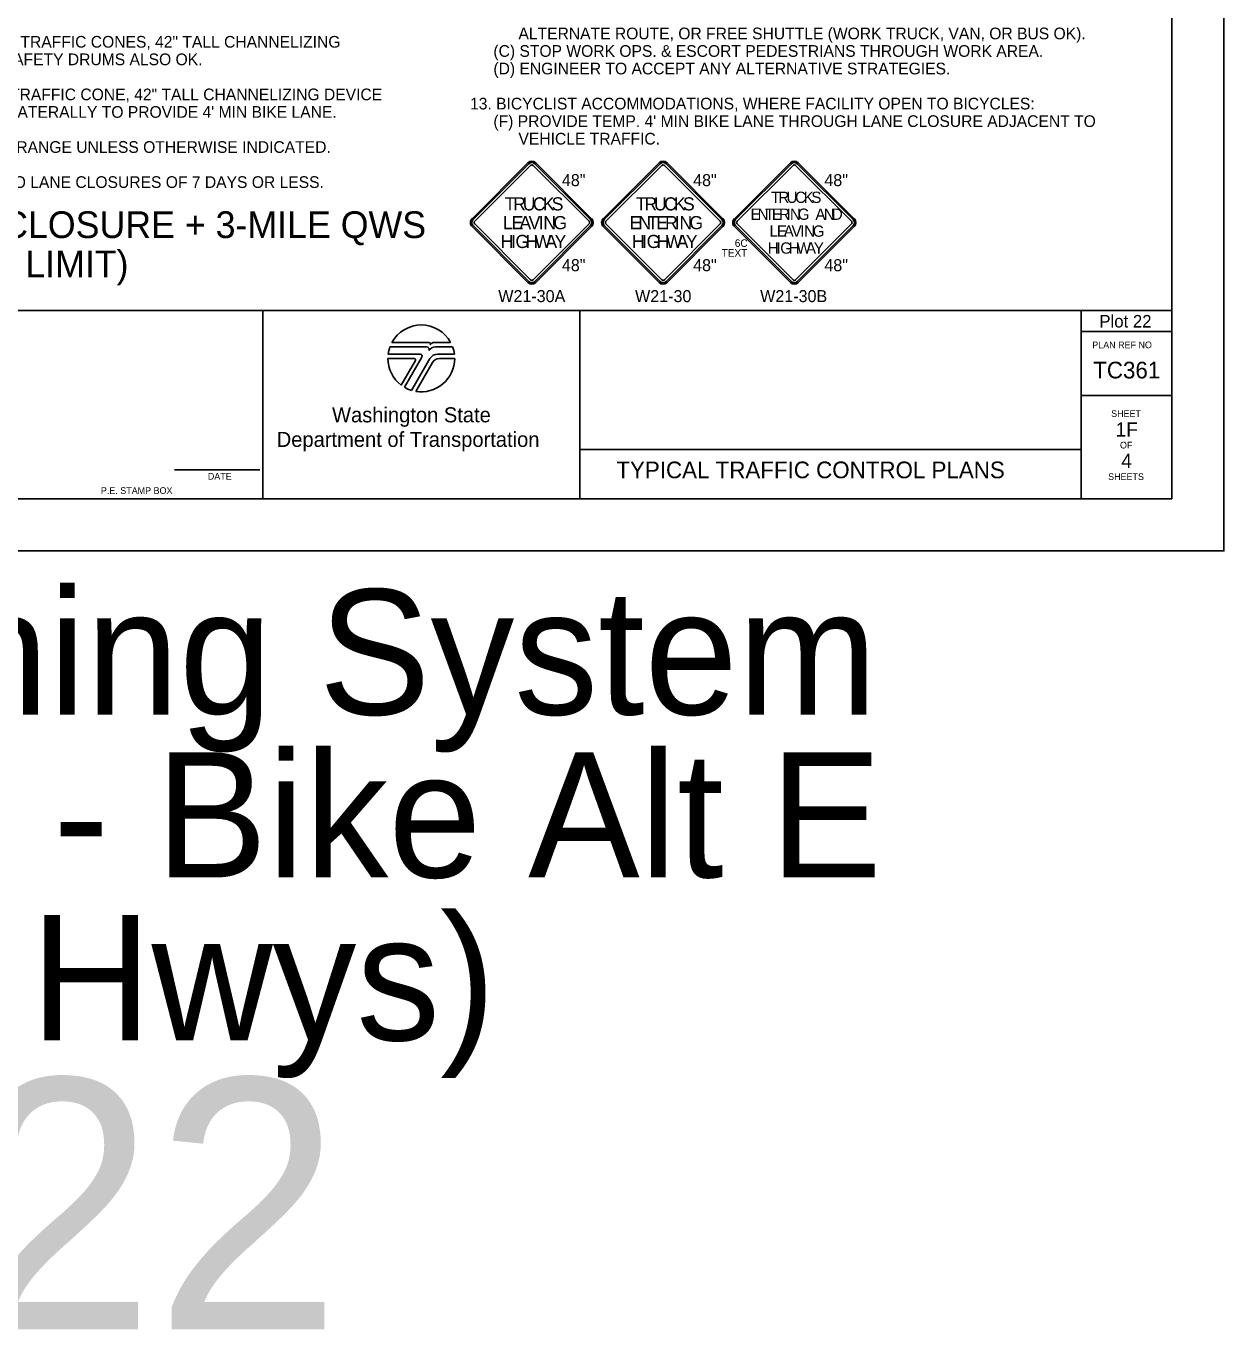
# Model space of a CAD drawing. Extents: x 99958 to 100176, y 99935 to 100011.
# Drawn here: x 100028.89 to 100036.06, y 99935.01 to 99942.83 of the extents above; entities that cross this region are included whole.
import ezdxf

# ---------------------------------------------------------------- set-up
doc = ezdxf.new("R2010")
doc.units = 0
for name, color, linetype in [('SH_DE_DetailHeading1Text', 7, 'Continuous'), ('SH_GI_GeneralNotesBodyText', 7, 'Continuous'), ('SH_GI_PlotLimits', 7, 'Continuous'), ('SH_GI_SheetBorder', 7, 'Continuous'), ('SH_GI_SheetLocationText', 7, 'Continuous'), ('SH_GI_SheetTextInCells', 7, 'Continuous'), ('SH_GI_TitleBlockText', 7, 'Continuous'), ('SH_GI_WSDOTLogo', 7, 'Continuous'), ('TR_SN_ConstructionSigns', 7, 'Continuous')]:
    doc.layers.add(name, color=color, linetype=linetype)

msp = doc.modelspace()

# ---------------------------------------------------------------- linework, layer by layer
at = {"layer": 'SH_GI_PlotLimits'}
msp.add_lwpolyline([(100019.0625, 99939.6875), (100036.0625, 99939.6875), (100036.0625, 99950.6875), (100019.0625, 99950.6875)], close=True, dxfattribs=at)
at = {"layer": 'SH_GI_SheetBorder'}
for p, q in [((100035.75, 99950.375), (100035.75, 99940)), ((100020, 99941.1259), (100035.75, 99941.1259)), ((100030.3089, 99941.1259), (100030.3089, 99940)), ((100032.2055, 99941.1259), (100032.2055, 99940)), ((100035.2079, 99941.1259), (100035.2079, 99940)), ((100035.2079, 99941.0008), (100035.75, 99941.0008)), ((100035.2079, 99940.6176), (100035.75, 99940.6176)), ((100032.2055, 99940.2955), (100035.2079, 99940.2955)), ((100029.7797, 99940.1733), (100030.2914, 99940.1733)), ((100020, 99940), (100035.75, 99940))]:
    msp.add_line(p, q, dxfattribs=at)
at = {"layer": 'SH_GI_WSDOTLogo'}
for p, q in [((100031.2894, 99940.9094), (100031.0697, 99940.9094)), ((100031.303, 99940.9354), (100031.0815, 99940.9354)), ((100031.433, 99940.9354), (100031.3351, 99940.9354)), ((100031.343, 99940.9094), (100031.3429, 99940.9094)), ((100031.4448, 99940.9094), (100031.343, 99940.9094)), ((100031.0572, 99940.84), (100031.2148, 99940.84)), ((100031.059, 99940.8661), (100031.2496, 99940.8661)), ((100031.222, 99940.8277), (100031.1364, 99940.6807)), ((100031.261, 99940.8464), (100031.1567, 99940.6672)), ((100031.1989, 99940.6487), (100031.3089, 99940.839)), ((100031.3558, 99940.8661), (100031.4555, 99940.8661)), ((100031.3655, 99940.8394), (100031.4572, 99940.8394)), ((100031.2244, 99940.6428), (100031.3242, 99940.8156))]:
    msp.add_line(p, q, dxfattribs=at)
for centre, radius, start, end in [((100031.2572, 99940.84), 0.2, 28.47865, 151.53204), ((100031.2572, 99940.84), 0.2, 159.69598, 172.50569), ((100031.2894, 99940.8946), 0.0148, 327.8418, 89.99855), ((100031.3429, 99940.861), 0.0484, 89.99529, 147.82376), ((100031.303, 99940.9263), 0.00903, 329.87418, 90.00328), ((100031.3352, 99940.9066), 0.0287, 90.00721, 148.16763), ((100031.2572, 99940.84), 0.2, 7.49431, 20.29406), ((100031.2572, 99940.84), 0.2, 179.99864, 232.84327), ((100031.2149, 99940.8318), 0.0082, 329.74356, 90), ((100031.2572, 99940.84), 0.2, 260.54554, 359.80857), ((100031.2497, 99940.853), 0.0131, 329.76834, 90), ((100031.3558, 99940.8119), 0.0542, 90, 149.99738), ((100031.3654, 99940.7918), 0.0476, 90, 150.05432), ((100031.2572, 99940.84), 0.2, 239.79292, 253.0448)]:
    msp.add_arc(centre, radius, start, end, dxfattribs=at)
at = {"layer": 'TR_SN_ConstructionSigns'}
for p, q in [((100031.8955, 99942.0107), (100031.5613, 99941.6766)), ((100031.9014, 99942.0048), (100031.5673, 99941.6707)), ((100032.2713, 99941.6707), (100031.9372, 99942.0048)), ((100032.2773, 99941.6766), (100031.9432, 99942.0107)), ((100032.6812, 99942.0107), (100032.3471, 99941.6766)), ((100032.6871, 99942.0048), (100032.353, 99941.6707)), ((100033.057, 99941.6707), (100032.7229, 99942.0048)), ((100033.063, 99941.6766), (100032.7289, 99942.0107)), ((100033.4669, 99942.0107), (100033.1328, 99941.6766)), ((100033.4729, 99942.0048), (100033.1387, 99941.6707)), ((100033.8428, 99941.6707), (100033.5087, 99942.0048)), ((100033.8487, 99941.6766), (100033.5146, 99942.0107)), ((100031.5773, 99941.6607), (100031.9114, 99941.9948)), ((100031.9273, 99941.9948), (100032.2614, 99941.6607)), ((100032.363, 99941.6607), (100032.6971, 99941.9948)), ((100032.713, 99941.9948), (100033.0471, 99941.6607)), ((100033.1487, 99941.6607), (100033.4828, 99941.9948)), ((100033.4987, 99941.9948), (100033.8328, 99941.6607)), ((100031.5613, 99941.6289), (100031.8955, 99941.2948)), ((100031.5673, 99941.6349), (100031.9014, 99941.3008)), ((100031.9114, 99941.3107), (100031.5773, 99941.6448)), ((100032.2614, 99941.6448), (100031.9273, 99941.3107)), ((100031.9372, 99941.3008), (100032.2713, 99941.6349)), ((100031.9432, 99941.2948), (100032.2773, 99941.6289)), ((100032.3471, 99941.6289), (100032.6812, 99941.2948)), ((100032.353, 99941.6349), (100032.6871, 99941.3008)), ((100032.6971, 99941.3107), (100032.363, 99941.6448)), ((100033.0471, 99941.6448), (100032.713, 99941.3107)), ((100032.7229, 99941.3008), (100033.057, 99941.6349)), ((100032.7289, 99941.2948), (100033.063, 99941.6289)), ((100033.1328, 99941.6289), (100033.4669, 99941.2948)), ((100033.1387, 99941.6349), (100033.4729, 99941.3008)), ((100033.4828, 99941.3107), (100033.1487, 99941.6448)), ((100033.8328, 99941.6448), (100033.4987, 99941.3107)), ((100033.5087, 99941.3008), (100033.8428, 99941.6349)), ((100033.5146, 99941.2948), (100033.8487, 99941.6289))]:
    msp.add_line(p, q, dxfattribs=at)
for centre, radius, start, end in [((100031.9193, 99941.9869), 0.0338, 45, 135), ((100031.9193, 99941.9869), 0.0253, 45, 135), ((100031.9193, 99941.9869), 0.0113, 45, 135), ((100032.705, 99941.9869), 0.0338, 45, 135), ((100032.705, 99941.9869), 0.0253, 45, 135), ((100032.705, 99941.9869), 0.0113, 45, 135), ((100033.4908, 99941.9869), 0.0338, 45, 135), ((100033.4908, 99941.9869), 0.0253, 45, 135), ((100033.4908, 99941.9869), 0.0113, 45, 135), ((100031.5852, 99941.6528), 0.0338, 135, 225.00001), ((100031.5852, 99941.6528), 0.0253, 135, 225.00001), ((100031.5852, 99941.6528), 0.0113, 135, 225.00001), ((100032.2534, 99941.6528), 0.0113, 315.00002, 45), ((100032.2534, 99941.6528), 0.0253, 315.00002, 45), ((100032.2534, 99941.6528), 0.0338, 315.00001, 45.00001), ((100032.3709, 99941.6528), 0.0338, 135, 225.00001), ((100032.3709, 99941.6528), 0.0253, 135, 225.00001), ((100032.3709, 99941.6528), 0.0113, 135, 225.00001), ((100033.0391, 99941.6528), 0.0113, 315.00002, 45), ((100033.0391, 99941.6528), 0.0253, 315.00002, 45), ((100033.0391, 99941.6528), 0.0338, 315.00001, 45.00001), ((100033.1566, 99941.6528), 0.0338, 135, 225.00001), ((100033.1566, 99941.6528), 0.0253, 135, 225.00001), ((100033.1566, 99941.6528), 0.0113, 135, 225.00001), ((100033.8249, 99941.6528), 0.0113, 315.00002, 45), ((100033.8249, 99941.6528), 0.0253, 315.00002, 45), ((100033.8249, 99941.6528), 0.0338, 315.00001, 45.00001), ((100031.9193, 99941.3187), 0.0338, 225.00001, 315.00001), ((100031.9193, 99941.3187), 0.0253, 225.00001, 315.00002), ((100031.9193, 99941.3187), 0.0113, 225.00001, 315.00002), ((100032.705, 99941.3187), 0.0338, 225.00001, 315.00001), ((100032.705, 99941.3187), 0.0253, 225.00001, 315.00002), ((100032.705, 99941.3187), 0.0113, 225.00001, 315.00002), ((100033.4908, 99941.3187), 0.0338, 225.00001, 315.00001), ((100033.4908, 99941.3187), 0.0253, 225.00001, 315.00002), ((100033.4908, 99941.3187), 0.0113, 225.00001, 315.00002)]:
    msp.add_arc(centre, radius, start, end, dxfattribs=at)

# ---------------------------------------------------------------- texts
at = {"layer": 'SH_DE_DetailHeading1Text'}
for s, p in [('4-LANE DIVIDED HIGHWAYS: SINGLE RIGHT LANE CLOSURE + 3-MILE QWS', (100023.5403, 99941.5606)), ('(45+ MPH, MAINTAIN EXISTING SPEED LIMIT)', (100024.8739, 99941.3259))]:
    msp.add_text(s, height=0.16, rotation=360, dxfattribs=at).set_placement(p)
at = {"layer": 'SH_GI_GeneralNotesBodyText'}
for s, p in [('ALTERNATE ROUTE, OR FREE SHUTTLE (WORK TRUCK, VAN, OR BUS OK).', (100031.839, 99942.7506)), ('7. 28" TRAFFIC CONES, 36" TRAFFIC CONES, 42" TALL CHANNELIZING ', (100027.6204, 99942.7006)), ('(C) STOP WORK OPS. & ESCORT PEDESTRIANS THROUGH WORK AREA.', (100031.689, 99942.6456)), ('DEVICES, OR TRAFFIC SAFETY DRUMS ALSO OK.', (100027.7004, 99942.5956)), ('(D) ENGINEER TO ACCEPT ANY ALTERNATIVE STRATEGIES.', (100031.689, 99942.5406)), ('8. 28" TRAFFIC CONE, 36" TRAFFIC CONE, 42" TALL CHANNELIZING DEVICE ', (100027.6204, 99942.3856)), ('13. BICYCLIST ACCOMMODATIONS, WHERE FACILITY OPEN TO BICYCLES:', (100031.549, 99942.3306)), ("OK. DEVICE MAY SHIFT LATERALLY TO PROVIDE 4' MIN BIKE LANE.", (100027.7004, 99942.2806)), ("(F) PROVIDE TEMP. 4' MIN BIKE LANE THROUGH LANE CLOSURE ADJACENT TO ", (100031.689, 99942.2256)), ('VEHICLE TRAFFIC.', (100031.839, 99942.1206)), ('9. SIGNS ARE BLACK ON ORANGE UNLESS OTHERWISE INDICATED.', (100027.6204, 99942.0706)), ('10. PLAN IS APPLICABLE TO LANE CLOSURES OF 7 DAYS OR LESS.', (100027.6204, 99941.8606))]:
    msp.add_text(s, height=0.07, rotation=360, dxfattribs=at).set_placement(p)
at = {"layer": 'SH_GI_SheetBorder'}
msp.add_text('PLAN REF NO', height=0.040032, dxfattribs=at).set_placement((100035.2747, 99940.9008))
at = {"layer": 'SH_GI_SheetLocationText'}
for s, height, p in [('Plot 22', 0.075, (100035.3171, 99941.025)), ('Plot 22', 0.075, (100035.3171, 99941.025)), ('3-Mile Queue Warning System', 0.75, (100020.3313, 99938.7071)), ('Right Lane Closure - Bike Alt E', 0.75, (100020.19, 99937.7321)), ('(45+ mph ML Hwys)', 0.75, (100022.7028, 99936.7571)), ('Plot 22', 1.5, (100024.5332, 99935.0267))]:
    msp.add_text(s, height=height, dxfattribs=at).set_placement(p)
at = {"layer": 'SH_GI_SheetTextInCells'}
for s, height, p in [('Washington State', 0.090072, (100030.7229, 99940.4571)), ('SHEET', 0.04003, (100035.3877, 99940.4896)), ('Department of Transportation', 0.090072, (100030.3916, 99940.3101)), ('OF', 0.04003, (100035.4406, 99940.3008)), ('DATE', 0.04003, (100029.9794, 99940.1141)), ('SHEETS', 0.04003, (100035.3698, 99940.112)), ('P.E. STAMP BOX', 0.040032, (100029.339, 99940.0286))]:
    msp.add_text(s, height=height, dxfattribs=at).set_placement(p)
at = {"layer": 'SH_GI_TitleBlockText'}
for s, height, p in [('TC361', 0.1, (100035.2803, 99940.72)), ('1F', 0.085, (100035.4148, 99940.3723)), ('TYPICAL TRAFFIC CONTROL PLANS', 0.1, (100032.4251, 99940.1224)), ('4', 0.085, (100035.4485, 99940.1843))]:
    msp.add_text(s, height=height, dxfattribs=at).set_placement(p)
at = {"layer": 'TR_SN_ConstructionSigns'}
for s, p in [('48"', (100032.0991, 99941.8713)), ('48"', (100032.8848, 99941.8713)), ('48"', (100033.6706, 99941.8713)), ('48"', (100032.0991, 99941.3622)), ('48"', (100032.8848, 99941.3622)), ('48"', (100033.6706, 99941.3622)), ('W21-30A', (100031.7182, 99941.1769)), ('W21-30', (100032.5373, 99941.1769)), ('W21-30B', (100033.2863, 99941.1769))]:
    msp.add_text(s, height=0.072, rotation=360, dxfattribs=at).set_placement(p)
for s, height, p in [('T', 0.0787, (100031.7563, 99941.7259)), ('R', 0.0787, (100031.8075, 99941.7259)), ('U', 0.0787, (100031.865, 99941.7259)), ('C', 0.0787, (100031.9248, 99941.7259)), ('K', 0.0787, (100031.9847, 99941.7259)), ('S', 0.0787, (100032.0382, 99941.7259)), ('T', 0.0787, (100032.542, 99941.7259)), ('R', 0.0787, (100032.5932, 99941.7259)), ('U', 0.0787, (100032.6507, 99941.7259)), ('C', 0.0787, (100032.7106, 99941.7259)), ('K', 0.0787, (100032.7704, 99941.7259)), ('S', 0.0787, (100032.824, 99941.7259)), ('T', 0.0675, (100033.351, 99941.7709)), ('R', 0.0675, (100033.3949, 99941.7709)), ('U', 0.0675, (100033.4442, 99941.7709)), ('C', 0.0675, (100033.4955, 99941.7709)), ('K', 0.0675, (100033.5468, 99941.7709)), ('S', 0.0675, (100033.5927, 99941.7709)), ('L', 0.0787, (100031.7465, 99941.6134)), ('E', 0.0787, (100031.7977, 99941.6134)), ('A', 0.0787, (100031.8449, 99941.6134)), ('V', 0.0787, (100031.9, 99941.6134)), ('I', 0.0787, (100031.9599, 99941.6134)), ('N', 0.0787, (100031.9882, 99941.6134)), ('G', 0.0787, (100032.0481, 99941.6134)), ('E', 0.0787, (100032.5034, 99941.6134)), ('N', 0.0787, (100032.557, 99941.6134)), ('T', 0.0787, (100032.6121, 99941.6134)), ('E', 0.0787, (100032.6633, 99941.6134)), ('R', 0.0787, (100032.7169, 99941.6134)), ('I', 0.0787, (100032.7743, 99941.6134)), ('N', 0.0787, (100032.8027, 99941.6134)), ('G', 0.0787, (100032.8625, 99941.6134)), ('E', 0.0675, (100033.2286, 99941.6696)), ('N', 0.0675, (100033.271, 99941.6696)), ('T', 0.0675, (100033.3154, 99941.6696)), ('E', 0.0675, (100033.3565, 99941.6696)), ('R', 0.0675, (100033.3989, 99941.6696)), ('I', 0.0675, (100033.4448, 99941.6696)), ('N', 0.0675, (100033.4646, 99941.6696)), ('G', 0.0675, (100033.5118, 99941.6696)), ('A', 0.0675, (100033.6171, 99941.6696)), ('N', 0.0675, (100033.667, 99941.6696)), ('D', 0.0675, (100033.7152, 99941.6696)), ('L', 0.0675, (100033.3426, 99941.5684)), ('E', 0.0675, (100033.3865, 99941.5684)), ('A', 0.0675, (100033.427, 99941.5684)), ('V', 0.0675, (100033.4742, 99941.5684)), ('I', 0.0675, (100033.5255, 99941.5684)), ('N', 0.0675, (100033.5498, 99941.5684)), ('G', 0.0675, (100033.6011, 99941.5684)), ('H', 0.0787, (100031.7327, 99941.5009)), ('I', 0.0787, (100031.7941, 99941.5009)), ('G', 0.0787, (100031.8209, 99941.5009)), ('H', 0.0787, (100031.8807, 99941.5009)), ('W', 0.0787, (100031.9359, 99941.5009)), ('A', 0.0787, (100032.0004, 99941.5009)), ('Y', 0.0787, (100032.0556, 99941.5009)), ('H', 0.0787, (100032.5184, 99941.5009)), ('I', 0.0787, (100032.5798, 99941.5009)), ('G', 0.0787, (100032.6066, 99941.5009)), ('H', 0.0787, (100032.6665, 99941.5009)), ('W', 0.0787, (100032.7216, 99941.5009)), ('A', 0.0787, (100032.7862, 99941.5009)), ('Y', 0.0787, (100032.8413, 99941.5009)), ('6C', 0.045, (100033.1343, 99941.5077)), ('H', 0.0675, (100033.3308, 99941.4671)), ('I', 0.0675, (100033.3834, 99941.4671)), ('G', 0.0675, (100033.4064, 99941.4671)), ('H', 0.0675, (100033.4577, 99941.4671)), ('W', 0.0675, (100033.5049, 99941.4671)), ('A', 0.0675, (100033.5603, 99941.4671)), ('Y', 0.0675, (100033.6075, 99941.4671)), ('TEXT', 0.045, (100033.0554, 99941.4491))]:
    msp.add_text(s, height=height, dxfattribs=at).set_placement(p)

doc.saveas('drawing.dxf')
